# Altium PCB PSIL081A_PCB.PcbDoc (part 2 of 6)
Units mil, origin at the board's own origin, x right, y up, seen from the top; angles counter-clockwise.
Board outline 14000 x 8000 mil, 10 copper layers (Top Layer, Signal Layer 1, Signal Layer 2, Signal Layer 3, Signal Layer 4, Signal Layer 5, Signal Layer 6, Signal Layer 7, Signal Layer 8, Bottom Layer), stack 60.9 mil thick; 433 components, 510 nets, 1716 pads, 590 vias.
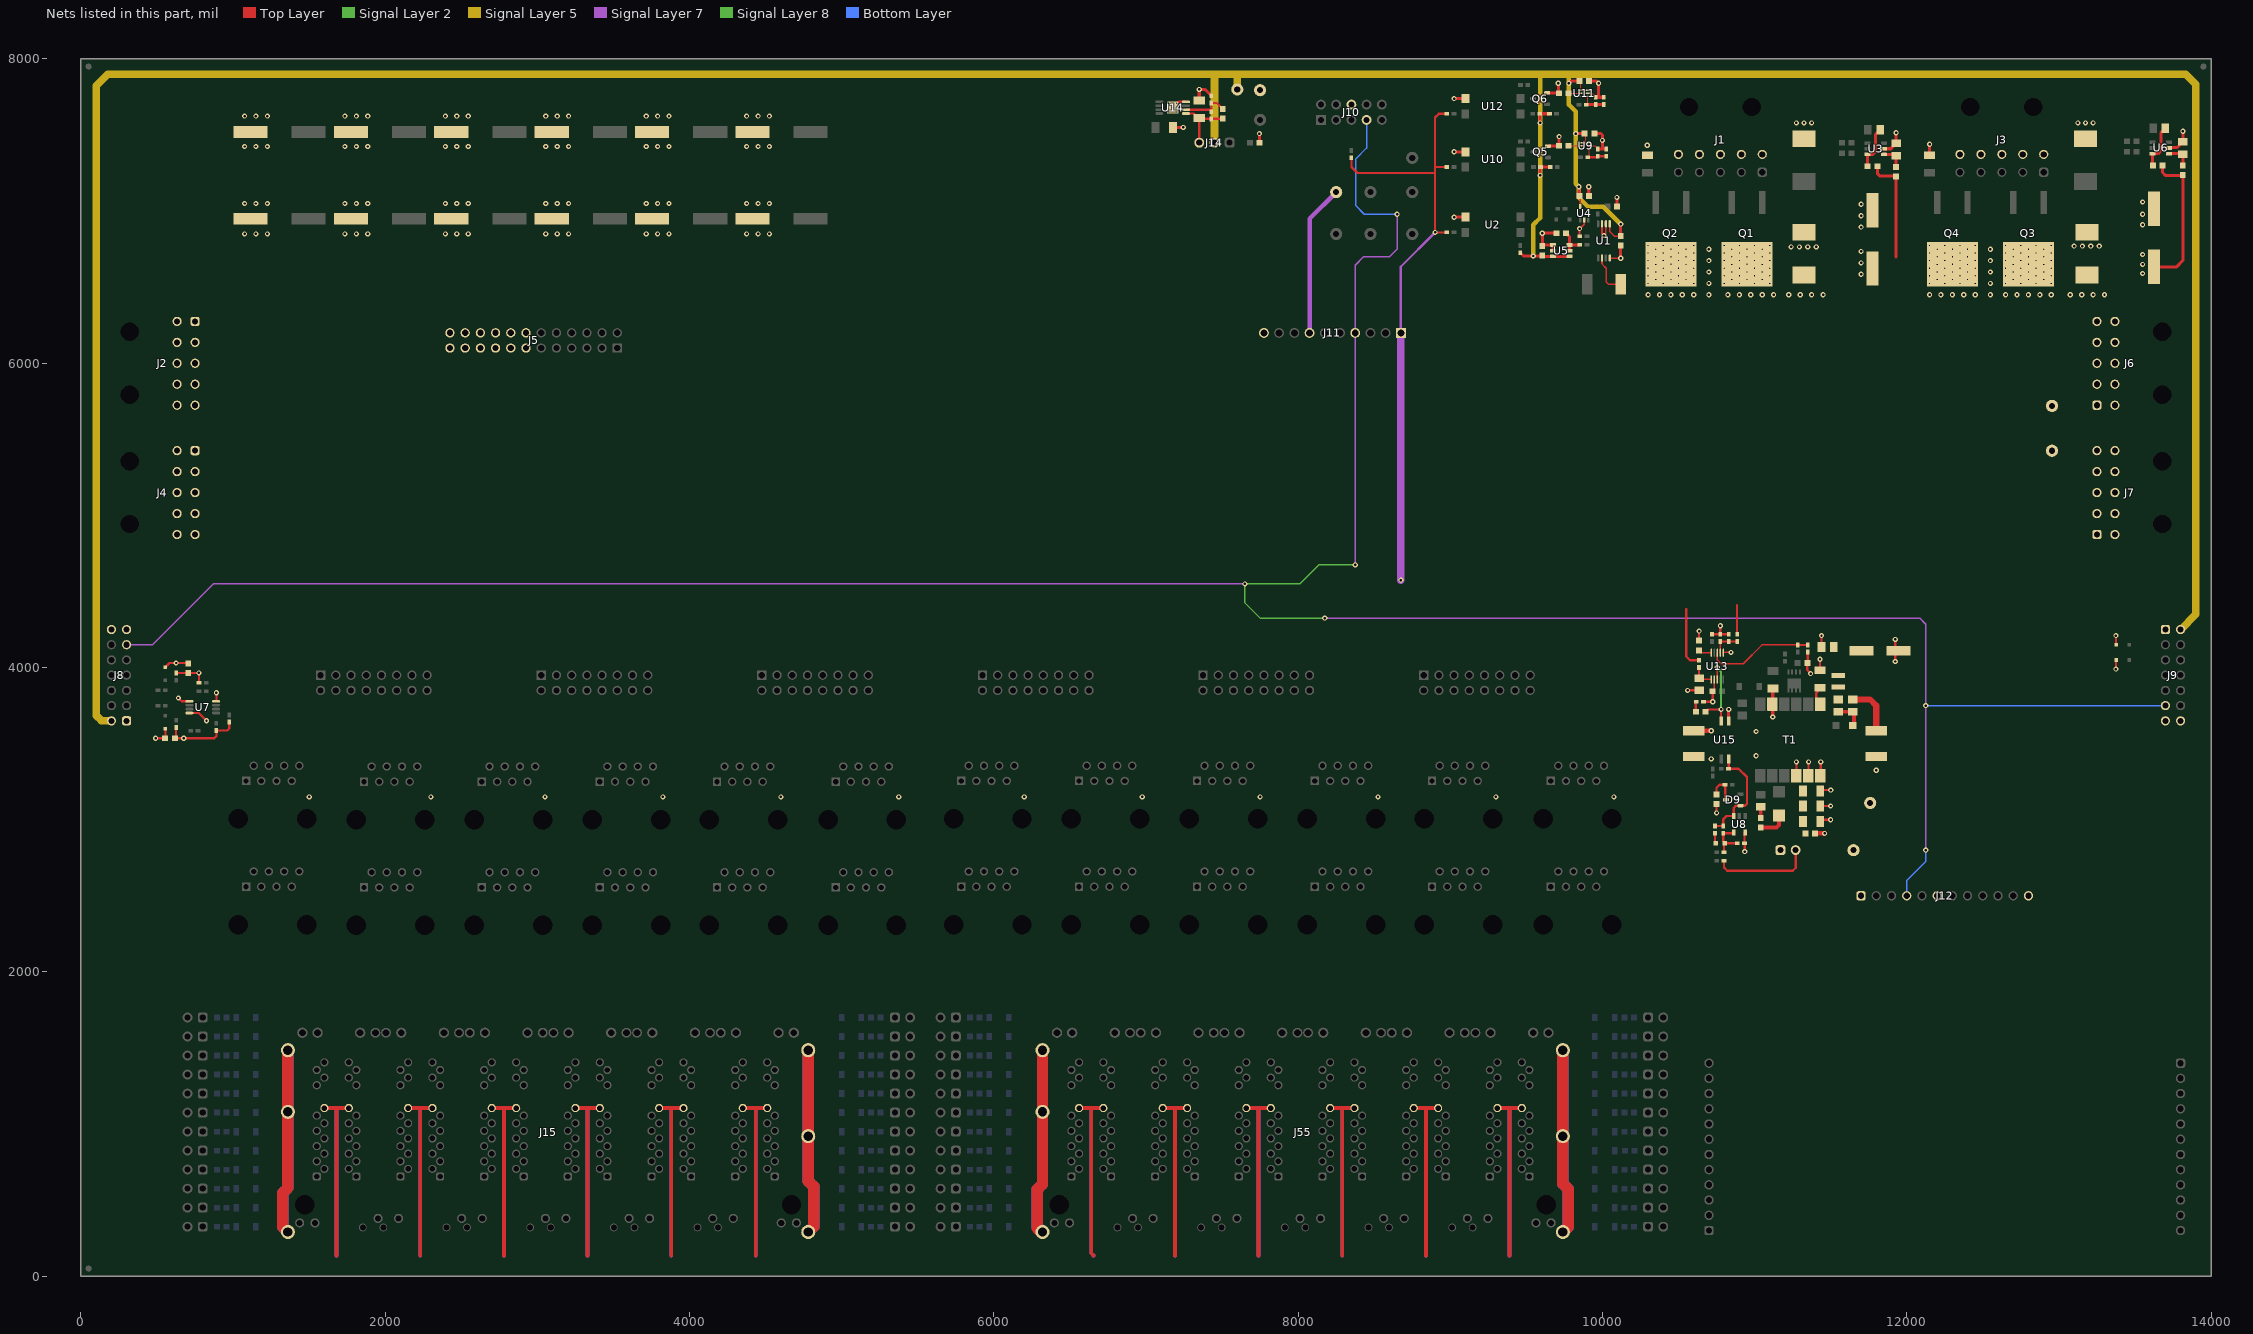
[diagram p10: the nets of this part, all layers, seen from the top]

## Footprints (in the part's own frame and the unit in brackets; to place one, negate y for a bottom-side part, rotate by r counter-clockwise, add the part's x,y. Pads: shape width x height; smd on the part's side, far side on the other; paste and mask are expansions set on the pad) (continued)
Samtec_SSW-112-21-x-S [mm] "Receptacle, 2.54mm, 12x1, TH"
  rrect50% 1.56x1.56 hole 1.04: 1(-13.97,0)
  round 1.56 hole 1.04: 2(-11.43,0) 3(-8.89,0) 4(-6.35,0) 5(-3.81,0) 6(-1.27,0) 7(1.27,0) 8(3.81,0) 9(6.35,0) 10(8.89,0) 11(11.43,0) 12(13.97,0)
  body extent -15.49,-1.21 15.49,1.21, height 8.51
Samtec_TST-107-01-G-D [mm] "Header(shrouded), 2.54mm, 7x2, TH"
  rrect50% 1.53x1.53 hole 1.02: 1(-1.27,7.62)
  round 1.53 hole 1.02: 2(1.27,7.62) 3(-1.27,5.08) 4(1.27,5.08) 5(-1.27,2.54) 6(1.27,2.54) 7(-1.27,0) 8(1.27,0) 9(-1.27,-2.54) 10(1.27,-2.54) 11(-1.27,-5.08) 12(1.27,-5.08) 13(-1.27,-7.62) 14(1.27,-7.62)
  silkscreen extent -4.9,-12.7 4.83,12.7, body extent -4.44,-12.7 4.84,12.7, height 9.27
SM_RADIAL_E [mm] "8 x 6.2mm:  Panasonic E"
  rect 4x1.6 smd: 1(-3.1,0) 2(3.1,0)
  silkscreen extent -4.25,-4.25 4.25,4.25, body extent -4.25,-4.25 4.25,4.25, height 6.5
SM_RADIAL_H13 [mm] "12.5 x 13.5mm:  Panasonic H13"
  rect 5.7x2 smd: 1(-4.85,0) 2(4.85,0)
  silkscreen extent -6.85,-6.85 6.85,6.85, body extent -6.85,-6.85 6.85,6.85, height 14
SMA [mm] "Molded Diode, 2-Leads, Body 4.3x2.6mm, IPC Medium Density, based on OnSemi component dimensions and land pattern"
  rect 2x2 smd: 1(-2,0) 2(2,0)
  silkscreen extent -3.66,-1.57 2.79,1.57, body extent -2.6,-1.3 2.6,1.3, height 2.42
SMC [mil] "Molded Diode, 2-Leads, Body 6.9x5.8mm, IPC Medium Density, based on OnSemi component dimensions and land patterns"
  rect 110x150 smd: 1(-140.49,0) 2(140.49,0)
  silkscreen extent -221,-123 189,124, body extent -156,-116 156,116, height 91
SOD-123 [mm] "On Semi recommended land pattern"
  rect 0.915x1.22 smd: 1(-1.637,0) 2(1.637,0)
  silkscreen extent -2.74,-1.17 2.03,1.17, body extent -1.93,-0.9 1.93,0.9, height 1.35
SOD-123F [mm] "NXP recommended land pattern"
  rect 1.2x1.2 smd paste-0.05: 1(-1.4,0) 2(1.4,0)
  silkscreen extent -2.64,-1.12 2.01,1.12, body extent -1.8,-0.85 1.8,0.85, height 1.2
SOD-323 [mm] "NXP recommended land pattern"
  rect 0.6x0.6 smd paste-0.05: 1(-1.1,0) 2(1.1,0)
  silkscreen extent -2.06,-0.86 1.53,0.86, body extent -1.3,-0.67 1.3,0.68, height 1.1
SOT-23 [mm] "SOT23, 3-Leads, Body 2.9x1.3mm, Pitch 0.95mm, Lead Span 2.5mm, IPC Medium Density"
  rrect50% 1x0.6 smd: 1(-1.2,0.95) 2(-1.2,-0.95) 3(1.2,0)
  silkscreen extent -1.62,-1.5 0.7,1.5, body extent -1.16,-1.45 1.21,1.45, height 1
SPC02SYAN [mil] "SULLINS"
  round 1 on Mech3: 0(0,0)
  body extent -98,-47 99,47, height 366
TI_Stacked_Overlay_Small [mil]
  silkscreen extent -418,-98 418,98
TSW-102-07-G-S [mm] "Samtec 100mil, 1x2, 230 mil above insulator"
  rrect50% 1.65x1.65 hole 1.016: 1(-1.27,0)
  round 1.65 hole 1.016: 2(1.27,0)
  body extent -2.54,-1.27 2.54,1.27, height 8.38
TSW-103-07-G-S [mm] "Samtec 100mil, 1x3, 230 mil above insulator"
  rrect50% 1.65x1.65 hole 1.016: 1(-2.54,0)
  round 1.65 hole 1.016: 2(0,0) 3(2.54,0)
  body extent -3.81,-1.27 3.81,1.27, height 8.38
WE-MAPI_2510 [mm] "SMD, 2-Leads, Body 2.7x2.2mm"
  rect 0.85x2.3 smd: 1(-0.975,0) 2(0.975,0)
  silkscreen extent -0.15,-1.1 0.15,1.1, body extent -1.25,-1 1.25,1, height 1
WEEE_Minimum [mil] "WEEElie bin"
  silkscreen extent -95,-172 99,104
Wurth_EP11_5 [mm] "SMD, 12-Leads, Body 9.2x12.9mm, Pitch 2mm"
  rrect6% 2.25x1.75 smd: 1(-5.975,5) 2(-5.975,3) 3(-5.975,1) 4(-5.975,-1) 5(-5.975,-3) 6(-5.975,-5) 7(5.975,-5) 8(5.975,-3) 9(5.975,-1) 10(5.975,1) 11(5.975,3) 12(5.975,5)
  body extent -6.5,-6.45 6.5,6.45, height 6.2

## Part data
C1 C6: library part CMP-0011225-2, "CAP, AL, 47 uF, 100 V, +/- 20%, 0.32 ohm, AEC-Q200 Grade 2, SMD", Cap_Case=H13, Manufacturer=Panasonic, Supplier Part Number 1=PCE3497CT-ND, Tolerance_%=20%, Value1="0.32 ohm", Value2=100V, ValueDisplayed=47uF
C2 C5 C23 C24 C28 C30 C54 C55: library part CMP-0006829-4, "CAP, CERM, 0.1 uF, 16 V, +/- 10%, X7R, 0603", Cap_Case=0603, Manufacturer="Wurth Elektronik", Supplier Part Number 1=710-885012206046, TempCo=X7R, Tolerance_%=10%, Value1=Unknown, Value2=16V, ValueDisplayed=0.1uF
C3 C9 C32 C46: library part CMP-0750068-1, "CAP, CERM, 1 µF, 100 V,+/- 10%, X7R, 1206", Cap_Case=1206, Manufacturer=AVX, TempCo=X7R, Tolerance_%=10%, Value2=100V, ValueDisplayed=1µF
C4 C10 C33 C37 C53 C56 C57: library part CMP-0007886-2, "CAP, CERM, 0.1 uF, 100 V, +/- 10%, X7R, 0805", Cap_Case=0805, Manufacturer=TDK, Supplier Part Number 1=445-1418-1-ND, TempCo=X7R, Tolerance_%=10%, Value1="0.020726 ohm", Value2=100V, ValueDisplayed=0.1uF
C7 C8: library part CMP-0007138-4, "CAP, CERM, 0.47 uF, 16 V, +/- 10%, X7R, AEC-Q200 Grade 1, 0603", Cap_Case=0603, Manufacturer=MuRata, Supplier Part Number 1=490-4775-1-ND, TempCo=X7R, Tolerance_%=10%, Value1=Unknown, Value2=16V, ValueDisplayed=0.47uF
C11 C12 C13 C14 C15 C16 C17 C18 C19 C20 C21 C22: library part CMP-0011226-2, "CAP, AL, 68 uF, 100 V, +/- 20%, 0.32 ohm, AEC-Q200 Grade 2, SMD", Cap_Case=H13, Manufacturer=Panasonic, Supplier Part Number 1=PCE3498CT-ND, Tolerance_%=20%, Value1="0.32 ohm", Value2=100V, ValueDisplayed=68uF
C25 C26: library part CMP-0006822-4, "CAP, CERM, 100 pF, 50 V, +/- 5%, C0G/NP0, 0603", Cap_Case=0603, Manufacturer="Wurth Elektronik", TempCo=C0G/NP0, Tolerance_%=5%, Value1=Unknown, Value2=50V, ValueDisplayed=100pF
C27 C29 C38: library part CMP-0006229-2, "CAP, CERM, 1000 pF, 25 V, +/- 10%, X7R, 0402", Cap_Case=0402, Manufacturer="Wurth Elektronik", Supplier Part Number 1=710-885012205044, TempCo=X7R, Tolerance_%=10%, Value1=Unknown, Value2=25V, ValueDisplayed=1000pF
C31: library part CMP-0064933-4, "CAP, CERM, 1000 pF, 50 V,+/- 10%, X7R, 0603", Cap_Case=0603, Manufacturer="Wurth Elektronik", Supplier Part Number 1=732-8001-1-ND, TempCo=X7R, Tolerance_%=10%, Value1=Unknown, Value2=50V, ValueDisplayed=1000pF
C34 C35 C36 C48: library part CMP-0009020-2, "CAP, CERM, 22 uF, 6.3 V, +/- 20%, X5R, 1206", Cap_Case=1206, Manufacturer="Taiyo Yuden", Supplier Part Number 1=1463395, TempCo=X5R, Tolerance_%=20%, Value1="0.012 ohm", Value2=6.3V, ValueDisplayed=22uF
C39: library part CMP-0006836-4, "CAP, CERM, 0.022 uF, 50 V, +/- 10%, X7R, 0603", Cap_Case=0603, Manufacturer="Wurth Elektronik", TempCo=X7R, Tolerance_%=10%, Value1=Unknown, Value2=50V, ValueDisplayed=0.022uF
C40 C49: library part CMP-0006831-4, "CAP, CERM, 1 uF, 16 V, +/- 10%, X7R, 0603", Cap_Case=0603, Manufacturer="Wurth Elektronik", Supplier Part Number 1=710-885012206052, TempCo=X7R, Tolerance_%=10%, Value1=Unknown, Value2=16V, ValueDisplayed=1uF
C41 C44: library part CMP-0006217-2, "CAP, CERM, 100 pF, 50 V, +/- 5%, C0G/NP0, 0402", Cap_Case=0402, Manufacturer="Wurth Elektronik", Supplier Part Number 1=732-7475-1-ND, TempCo=C0G/NP0, Tolerance_%=5%, Value1=Unknown, Value2=50V, ValueDisplayed=100pF
C42: library part CMP-0750070-1, "CAP, CERM, 10 µF, 16 V,+/- 10%, X7R, 1206", Cap_Case=1206, Manufacturer="Wurth Elektronik", TempCo=X7R, Tolerance_%=10%, Value2=16V, ValueDisplayed=10µF
C43: library part CMP-0750069-1, "CAP, CERM, 0.068 µF, 25 V,+/- 10%, X7R, 0603", Cap_Case=0603, Manufacturer="Wurth Elektronik", TempCo=X7R, Tolerance_%=10%, Value2=25V, ValueDisplayed=0.068µF
C45: library part CMP-0086483-1, "0.047µF ±10% 25V Ceramic Capacitor X7R 0603 (1608 Metric)", Manufacturer="Wurth Electronics", TempCo=15%, Tolerance_%=10%
C47: library part CMP-0750039-1, "CAP, CERM, 0.01 µF, 50 V,+/- 10%, X7R, 0603", Cap_Case=0603, Manufacturer="Wurth Elektronik", TempCo=X7R, Tolerance_%=10%, Value2=50V, ValueDisplayed=0.01µF
C50 C51: library part CMP-0009358-2, "CAP, CERM, 2200 pF, 2000 V, +/- 10%, X7R, 1812", Cap_Case=1812, Manufacturer=TDK, Supplier Part Number 1=445-2389-1-ND, TempCo=X7R, Tolerance_%=10%, Value1=Unknown, Value2=2000V, ValueDisplayed=2200pF
C52: library part CMP-0011189-2, "CAP, AL, 22 uF, 63 V, +/- 20%, 1.2 ohm, AEC-Q200 Grade 2, SMD", Cap_Case=E, Manufacturer=Panasonic, Supplier Part Number 1=PCE3820CT-ND, Tolerance_%=20%, Value1="1.2 ohm", Value2=63V, ValueDisplayed=22uF
C58: library part CMP-0007136-5, "CAP, CERM, 1 uF, 16 V, +/- 10%, X7R, AEC-Q200 Grade 1, 0603", Cap_Case=0603, Manufacturer=MuRata, Supplier Part Number 1=490-5241-6-ND, TempCo=X7R, Tolerance_%=10%, Value1=Unknown, Value2=16V, ValueDisplayed=1uF
D1 D4: library part CMP-0005716-3, "Diode, TVS, Uni, 58 V, 93.6 Vc, SMC", Manufacturer="Diodes Inc.", Value1=1500W
D2 D5: library part CMP-0028411-2, "Diode, Schottky, 100 V, 3 A, SMC", Manufacturer="Diodes Inc.", Value1=3A, Value2=0.79V
D3 D58 D59 D60 D61: library part CMP-0028458-2, "Diode, Schottky, 30 V, 0.2 A, SOD-323", Manufacturer="Diodes Inc.", Value1=0.2A, Value2=0.7V
D6: library part CMP-0028401-1, "Diode, Schottky, 30 V, 2 A, SMA", Manufacturer="Diodes Inc.", Supplier Part Number 1=B230A-FDICT-ND, Value1=2A, Value2=0.5V
D7: library part CMP-0750076-1, "Diode, Superfast Rectifier, 200 V, 0.7 A, SOD-123F", Manufacturer=Rohm, Value1=0.7A, Value2=0.85V
D8: library part CMP-0029032-1, "Diode, Switching, 100 V, 0.2 A, SOD-123", Manufacturer="ON Semiconductor", Supplier Part Number 1=MMSD4148T1GOSCT-ND, Value1=0.2A, Value2=1V
D9: library part CMP-0028456-1, "Diode, Schottky, 30 V, 0.2 A, SOT-23", Manufacturer="Diodes Inc.", Supplier Part Number 1=BAT54S-FDICT-ND, Value1=0.2A, Value2=0.65V
D10 D11 D12 D13 D14 D15 D16 D17 D18 D19 D20 D21 D22 D23 D24 D25 D26 D27 D28 D29 D30 D31 D32 D33 D34 D35 D36 D37 D38 D39 D40 D41 D42 D43 D44 D45 D46 D47 D48 D49 D50 D51 D52 D53 D54 D55 D56 D57: library part CMP-0005757-2, "Diode, Zener, 22 V, 500 mW, SOD-123", Manufacturer="Diodes Inc.", Power_W=500mW, Supplier Part Number 1=MMSZ5251B-FDICT-ND, Value1=0.5W
FID1 FID2 FID3 FID4 FID5 FID6: library part CMP-0077181-1, "Fiducial mark.  There is nothing to buy or mount.", Manufacturer=N/A
H1 H2 H3 H4 H5 H6 H7 H8 H9 H10 H11 H12: library part CMP-0079645-1, Manufacturer=3M, Supplier Part Number 1=SJ61A6-ND
J1 J2 J3 J4 J6 J7: library part CMP-0085662-1, "Header(shrouded), 3.5mm, 5x2, Gold, R/A, TH", Color=Black, Manufacturer=Molex, Voltage_V=400V
J5: library part CMP-0750080-1, "Receptacle, 2.54mm, 12x2, Gold, TH", Color=Black, Current_A=4.7A, Manufacturer=Samtec, Voltage_V=655V
J8 J9: library part CMP-0078831-2, "Header(shrouded), 2.54mm, 7x2, Gold, TH", Color=Black, Current_A=3.4A, Manufacturer=Samtec, Supplier Part Number 1=SAM10833-ND, Voltage_V=1kV
J10: library part CMP-0055448-2, "Header (shrouded), 100mil, 5x2, High-Temperature, Gold, TH", Manufacturer=3M, Supplier Part Number 1=MHC10K-ND
J11: library part CMP-0750079-1, "Receptacle, 2.54mm, 10x1, Gold, TH", Color=Black, Current_A=4.7A, Manufacturer=Samtec, Voltage_V=655V
J12 J95 J96: library part CMP-0750078-1, "Receptacle, 2.54mm, 12x1, Gold, TH", Color=Black, Current_A=4.7A, Manufacturer=Samtec, Voltage_V=655V
J13 J17 J19 J21 J22 J23 J24 J26 J28 J30 J31 J32 J33 J38 J40 J42 J43 J44 J45 J47 J49 J51 J52 J53 J54 J57 J59 J61 J62 J63 J64 J66 J68 J70 J71 J72 J73 J78 J80 J82 J83 J84 J85 J87 J89 J91 J92 J93 J94: library part CMP-0075405-2, "Header, 100mil, 2x1, Gold, TH", Color=Black, Current_A=6.3A, Manufacturer=Samtec, Supplier Part Number 1=SAM1029-02-ND, Voltage_V=550V
J14: library part CMP-0075407-2, "Header, 100mil, 3x1, Gold, TH", Color=Black, Current_A=6.3A, Manufacturer=Samtec, Supplier Part Number 1=SAM1029-03-ND, Voltage_V=550V
J15 J55: library part CMP-0081711-4, "12 Port RJ45, R/A, TH", Manufacturer="Pulse Engineering", Supplier Part Number 1=553-3937-ND
J16 J18 J20 J25 J27 J29 J37 J39 J41 J46 J48 J50 J56 J58 J60 J65 J67 J69 J77 J79 J81 J86 J88 J90: library part CMP-0055855-1, "RJ45, Vertical, TH", Manufacturer="Stewart Connector", Supplier Part Number 1=380-1050-ND
J34 J35 J36 J74 J75 J76: library part CMP-0750077-1, "Receptacle, 2.54mm, 8x2, Gold, TH", Color=Black, Current_A=4.7A, Manufacturer=Samtec, Voltage_V=655V
L1: library part CMP-0750073-1, "Inductor, Shielded, Metal Composite, 3.3 µH, 1.25 A, 0.264 ohm, SMD", Manufacturer="Wurth Elektronik", Value1="0.264 ohm", Value2=1.25A, ValueDisplayed=3.3µH
Logo1: library part CMP-0074838-1, "Texas Instrument Corporate Signature"
Logo2: library part CMP-0074844-1
Logo3: library part CMP-0074847-1, "FCC_disclaimer"
Logo4: library part CMP-0074769-1
Q1 Q2 Q3 Q4: library part CMP-0000966-3, "MOSFET, N-CH, 100 V, 200 A, KTT0002A (TO-263-2)", Alternate Manufacturer=None, Manufacturer="Texas Instruments", Supplier Part Number 1=296-41136-1-ND, Value2="118 nC"
Q5 Q6: library part CMP-0000419-2, "Transistor, NPN, 40 V, 0.2 A, SOT-23", Manufacturer="ON Semiconductor", Supplier Part Number 1=MMBT3904LT1GOSCT-ND, Value1="0.2 A", Value2=300
Q7: library part CMP-0001051-2, "MOSFET, N-CH, 150 V, 13 A, PG-TSDSON-8", Alternate Manufacturer=None, Manufacturer="Infineon Technologies", Supplier Part Number 1="BSZ900N15NS3 GCT-ND", Value2="5 nC"
R1 R6: library part CMP-0025700-4, "RES, 100, 5%, 0.1 W, AEC-Q200 Grade 0, 0603", Manufacturer=Vishay-Dale, Power_W=100mW, Supplier Part Number 1=541-100GCT-ND, TempCo="200 ppm/C", Tolerance_%=5%, Value2=0.1W, Value_Code=100R, ValueDisplayed=100
R2 R20 R23 R35 R45: library part CMP-0026071-3, "RES, 1.00 k, 1%, 0.063 W, AEC-Q200 Grade 0, 0402", Manufacturer=Vishay-Dale, Power_W=63mW, Supplier Part Number 1=541-1.00KLCT-ND, TempCo="100 ppm/C", Tolerance_%=1%, Value2=0.063W, Value_Code=1k00, ValueDisplayed=1.00k
R3 R21 R24: library part CMP-0026329-2, "RES, 3.01 k, 1%, 0.063 W, AEC-Q200 Grade 0, 0402", Manufacturer=Vishay-Dale, Power_W=63mW, Supplier Part Number 1=541-3.01KLCT-ND, TempCo="100 ppm/C", Tolerance_%=1%, Value2=0.063W, Value_Code=3k01, ValueDisplayed=3.01k
R4: library part CMP-0015822-2, "RES, 0.0005, 1%, 3 W, 2512", Manufacturer="Stackpole Electronics Inc", Power_W=3W, Supplier Part Number 1=HCS2512FTL500CT-ND, TempCo="115 ppm/C", Tolerance_%=1%, Value_Code=L5000, ValueDisplayed=0.0005
R5: library part CMP-0026367-2, "RES, 40.2 k, 1%, 0.063 W, AEC-Q200 Grade 0, 0402", Manufacturer=Vishay-Dale, Power_W=63mW, Supplier Part Number 1=541-40.2KLCT-ND, TempCo="100 ppm/C", Tolerance_%=1%, Value2=0.063W, Value_Code=40k2, ValueDisplayed=40.2k
R7 R9 R10 R11 R12 R13 R42 R43: library part CMP-0025958-3, "RES, 10.0 k, 1%, 0.063 W, AEC-Q200 Grade 0, 0402", Manufacturer=Vishay-Dale, Power_W=63mW, Supplier Part Number 1=541-10.0KLCT-ND, TempCo="100 ppm/C", Tolerance_%=1%, Value2=0.063W, Value_Code=10k0, ValueDisplayed=10.0k
R8: library part CMP-0026516-2, "RES, 6.65 k, 1%, 0.063 W, AEC-Q200 Grade 0, 0402", Manufacturer=Vishay-Dale, Power_W=63mW, Supplier Part Number 1=541-6.65KLCT-ND, TempCo="100 ppm/C", Tolerance_%=1%, Value2=0.063W, Value_Code=6k65, ValueDisplayed=6.65k
R14 R15 R18 R39 R44 R97 R104 R105: library part CMP-0026992-3, "RES, 0, 5%, 0.1 W, AEC-Q200 Grade 0, 0402", Manufacturer=Panasonic, Power_W=100mW, Supplier Part Number 1=P0.0JCT-ND, TempCo="600 ppm/C", Tolerance_%=5%, Value2=0.1W, Value_Code=0000, ValueDisplayed=0
R16 R17: library part CMP-0026404-2, "RES, 49.9, 1%, 0.063 W, AEC-Q200 Grade 0, 0402", Manufacturer=Vishay-Dale, Power_W=63mW, Supplier Part Number 1=541-49.9LCT-ND, TempCo="100 ppm/C", Tolerance_%=1%, Value2=0.063W, Value_Code=49R9, ValueDisplayed=49.9
R19 R22: library part CMP-0026414-2, "RES, 4.99 k, 1%, 0.063 W, AEC-Q200 Grade 0, 0402", Manufacturer=Vishay-Dale, Power_W=63mW, Supplier Part Number 1=541-4.99KLCT-ND, TempCo="100 ppm/C", Tolerance_%=1%, Value2=0.063W, Value_Code=4k99, ValueDisplayed=4.99k
R25 R26: library part CMP-0026158-2, "RES, 200 k, 1%, 0.063 W, AEC-Q200 Grade 0, 0402", Manufacturer=Vishay-Dale, Power_W=63mW, Supplier Part Number 1=541-200KLCT-ND, TempCo="100 ppm/C", Tolerance_%=1%, Value2=0.063W, Value_Code=200k
R27 R28: library part CMP-0026465-2, "RES, 5.36 k, 1%, 0.063 W, AEC-Q200 Grade 0, 0402", Manufacturer=Vishay-Dale, Power_W=63mW, Supplier Part Number 1=541-5.36KLCT-ND, TempCo="100 ppm/C", Tolerance_%=1%, Value2=0.063W, Value_Code=5k36, ValueDisplayed=5.36k
R29: library part CMP-0020567-3, "RES, 51, 5%, 0.125 W, AEC-Q200 Grade 0, 0805", Manufacturer=Vishay-Dale, Power_W=125mW, Supplier Part Number 1=541-51ACT-ND, TempCo="200 ppm/C", Tolerance_%=5%, Value2=0.125W, Value_Code=51R0, ValueDisplayed=51
R30: library part CMP-0020536-3, "RES, 39 k, 5%, 0.125 W, AEC-Q200 Grade 0, 0805", Manufacturer=Vishay-Dale, Power_W=125mW, Supplier Part Number 1=541-39KACT-ND, TempCo="200 ppm/C", Tolerance_%=5%, Value2=0.125W, Value_Code=39k0, ValueDisplayed=39k
R31 R34: library part CMP-0026827-3, "RES, 10, 5%, 0.063 W, AEC-Q200 Grade 0, 0402", Manufacturer=Vishay-Dale, Power_W=63mW, Supplier Part Number 1=541-10JCT-ND, TempCo="200 ppm/C", Tolerance_%=5%, Value2=0.063W, Value_Code=10R0, ValueDisplayed=10
R32 R46: library part CMP-0025950-3, "RES, 100 k, 1%, 0.063 W, AEC-Q200 Grade 0, 0402", Manufacturer=Vishay-Dale, Power_W=63mW, Supplier Part Number 1=541-100KLCT-ND, TempCo="100 ppm/C", Tolerance_%=1%, Value2=0.063W, Value_Code=100k
R33: library part CMP-0020497-3, "RES, 20, 5%, 0.125 W, AEC-Q200 Grade 0, 0805", Manufacturer=Vishay-Dale, Power_W=125mW, Supplier Part Number 1=541-20ACT-ND, TempCo="200 ppm/C", Tolerance_%=5%, Value2=0.125W, Value_Code=20R0, ValueDisplayed=20
R36: library part CMP-0026336-2, "RES, 3.57 k, 1%, 0.063 W, AEC-Q200 Grade 0, 0402", Manufacturer=Vishay-Dale, Power_W=63mW, Supplier Part Number 1=541-3.57KLCT-ND, TempCo="100 ppm/C", Tolerance_%=1%, Value2=0.063W, Value_Code=3k57, ValueDisplayed=3.57k
R37: library part CMP-0026201-2, "RES, 25.5 k, 1%, 0.063 W, AEC-Q200 Grade 0, 0402", Manufacturer=Vishay-Dale, Power_W=63mW, Supplier Part Number 1=541-25.5KLCT-ND, TempCo="100 ppm/C", Tolerance_%=1%, Value2=0.063W, Value_Code=25k5, ValueDisplayed=25.5k
R38: library part CMP-0022193-4, "RES, 1.74, 1%, 0.1 W, AEC-Q200 Grade 0, 0603", Manufacturer=Vishay-Dale, Power_W=100mW, Supplier Part Number 1=541-1.74HHCT-ND, TempCo="100 ppm/C", Tolerance_%=1%, Value2=0.1W, Value_Code=1R74, ValueDisplayed=1.74
R40: library part CMP-0026088-3, "RES, 1.50 k, 1%, 0.063 W, AEC-Q200 Grade 0, 0402", Manufacturer=Vishay-Dale, Power_W=63mW, Supplier Part Number 1=541-1.50KLCT-ND, TempCo="100 ppm/C", Tolerance_%=1%, Value2=0.063W, Value_Code=1k50, ValueDisplayed=1.50k
R41: library part CMP-0026185-2, "RES, 237, 1%, 0.063 W, AEC-Q200 Grade 0, 0402", Manufacturer=Vishay-Dale, Power_W=63mW, Supplier Part Number 1=541-237LCT-ND, TempCo="100 ppm/C", Tolerance_%=1%, Value2=0.063W, Value_Code=237R, ValueDisplayed=237
R47: library part CMP-0026469-2, "RES, 5.90 k, 1%, 0.063 W, AEC-Q200 Grade 0, 0402", Manufacturer=Vishay-Dale, Power_W=63mW, Supplier Part Number 1=541-5.90KLCT-ND, TempCo="100 ppm/C", Tolerance_%=1%, Value2=0.063W, Value_Code=5k90, ValueDisplayed=5.90k
R48: library part CMP-0026449-2, "RES, 54.9 k, 1%, 0.063 W, AEC-Q200 Grade 0, 0402", Manufacturer=Vishay-Dale, Power_W=63mW, Supplier Part Number 1=541-54.9KLCT-ND, TempCo="100 ppm/C", Tolerance_%=1%, Value2=0.063W, Value_Code=54k9, ValueDisplayed=54.9k
R49 R50 R51 R52 R53 R54 R55 R56 R57 R58 R59 R60 R61 R62 R63 R64 R65 R66 R67 R68 R69 R70 R71 R72 R73 R74 R75 R76 R77 R78 R79 R80 R81 R82 R83 R84 R85 R86 R87 R88 R89 R90 R91 R92 R93 R94 R95 R96: library part CMP-0022352-4, "RES, 35.7 k, 1%, 0.1 W, AEC-Q200 Grade 0, 0603", Manufacturer=Vishay-Dale, Power_W=100mW, Supplier Part Number 1=541-35.7KHCT-ND, TempCo="100 ppm/C", Tolerance_%=1%, Value2=0.1W, Value_Code=35k7, ValueDisplayed=35.7k
R98 R99 R100 R101 R102 R103: library part CMP-0025703-4, "RES, 10, 5%, 0.1 W, AEC-Q200 Grade 0, 0603", Manufacturer=Vishay-Dale, Power_W=100mW, Supplier Part Number 1=541-10GCT-ND, TempCo="200 ppm/C", Tolerance_%=5%, Value2=0.1W, Value_Code=10R0, ValueDisplayed=10
SH-J1 SH-J2 SH-J3 SH-J4 SH-J5 SH-J6 SH-J7 SH-J8 SH-J9 SH-J10 SH-J11 SH-J12 SH-J13 SH-J14 SH-J15 SH-J16 SH-J17 SH-J18 SH-J19 SH-J20 SH-J21 SH-J22 SH-J23 SH-J24 SH-J25 SH-J26 SH-J27 SH-J28 SH-J29 SH-J30 SH-J31 SH-J32 SH-J33 SH-J34 SH-J35 SH-J36 SH-J37 SH-J38 SH-J39 SH-J40 SH-J41 SH-J42 SH-J43 SH-J44 SH-J45 SH-J46 SH-J47 SH-J48 SH-J49 SH-J50: library part CMP-0003642-1, "Shunt, 100mil, Flash Gold, Black", Manufacturer="Sullins Connector Solutions", Supplier Part Number 1=S9001-ND
T1: library part CMP-0084630-1, "Transformer, 400 uH, SMT", Manufacturer="Wurth Elektronik", ValueDisplayed=400µH
TP1 TP8 TP10 TP11: library part CMP-0055137-1, "Test Point, Miniature, Red, TH", Color=Red, Manufacturer=Keystone, PartNumber=5000, Supplier Part Number 1=36-5000-ND
TP2 TP9 TP12 TP13: library part CMP-0055138-1, "Test Point, Miniature, Black, TH", Color=Black, Manufacturer=Keystone, PartNumber=5001, Supplier Part Number 1=36-5001-ND
TP3: library part CMP-0055141-1, "Test Point, Miniature, Yellow, TH", Color=Yellow, Manufacturer=Keystone, PartNumber=5004, Supplier Part Number 1=36-5004-ND
TP4 TP5 TP14: library part CMP-0055139-1, "Test Point, Miniature, White, TH", Color=White, Manufacturer=Keystone, PartNumber=5002, Supplier Part Number 1=36-5002-ND
TP6 TP7: library part CMP-0055140-1, "Test Point, Miniature, Orange, TH", Color=Orange, Manufacturer=Keystone, PartNumber=5003, Supplier Part Number 1=36-5003-ND
U1: library part CMP-0075735-1, "High/Low Side, Bi-Directional Zero-Drift Current Sense Amp w/ Enhanced PWM Rejection, PW0008A (TSSOP-8)", Alternate Manufacturer="Texas Instruments", Alternate PartNumber=INA240A2PW
U2 U10 U12: library part CMP-0006165-3, "Optocoupler, 5 kV, 300-600% CTR, SMT", Manufacturer="Fairchild Semiconductor", Supplier Part Number 1=FOD817DS-ND, Voltage_Isolation_Vrms=5kV
U3 U6: library part CMP-0066129-2, "High Side OR-ing FET Controller, DDC0006A (SOT-23-T-6)", Alternate Manufacturer="Texas Instruments"
U4: library part CMP-0085889-2, "Small-Size Micropower Low-Voltage Comparator, DCK0005A (SOT-SC70-5)", Alternate Manufacturer="Texas Instruments", Alternate PartNumber=TLV7021DCKT, Operating Temperature Range="-40 to 125 C", Rating=Catalog
U5: library part CMP-0083672-1, "2.5V Low-Drift Low-Power Small-Footprint Series Voltage Reference, DBV0006A (SOT-23-6)", Alternate Manufacturer="Texas Instruments", Operating Temperature Range="-40 to 125 C", Rating=Catalog
U7: library part CMP-0065788-2, "Level-Translating I2C Bus Repeater, DGK0008A (VSSOP-8)", Alternate Manufacturer="Texas Instruments"
U8: library part CMP-0032952-1, "Low Voltage Adjustable Precision Shunt Regulator, 39 ppm / degC, 15 mA, -40 to 85 degC, 5-pin SOT-23 (DBV), Green (RoHS & no Sb/Br)", Manufacturer="Texas Instruments", Rating=Catalog, Temp Coeff(Max)(ppm/ degree C)=129, Temp Coeff(Typ)(ppm/ degree C)=39
U9 U11: library part CMP-0074273-2, "Low Quiescent Current, 1% Accurate Supervisor with Programmable-Delay, DSE0006A (WSON-6)", Alternate Manufacturer="Texas Instruments", Alternate PartNumber=TPS389001DSET
U13: library part CMP-0066105-1, "13-100V Wide Vin, Current Mode PWM Boost Controller, DGS0010A (VSSOP-10)", Alternate Manufacturer="Texas Instruments"
U14: library part CMP-0035942-1, "Single Output LDO, 50 mA, Adjustable 1.175 to 90 V Output, 7 to 100 V Input, 8-pin MSOP (DGN), -40 to 125 degC, Green (RoHS & no Sb/Br)", Manufacturer="Texas Instruments"
U15: library part CMP-0006164-3, "Optocoupler, 3.75 kV, 80-160% CTR, SMT", Manufacturer="Fairchild Semiconductor", Supplier Part Number 1=HMHA2801A-ND, Voltage_Isolation_Vrms=3.75kV
ZZ2: library part CMP-0077236-1
ZZ3: library part CMP-0077237-1
ZZ4: library part CMP-0077238-1

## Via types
v1: diameter 34, hole 16, Top Layer to Bottom Layer, 429 vias
v2: diameter 26, hole 8, Top Layer to Bottom Layer, 156 vias
v3: diameter 19.68, hole 7.87, Top Layer to Bottom Layer, 5 vias

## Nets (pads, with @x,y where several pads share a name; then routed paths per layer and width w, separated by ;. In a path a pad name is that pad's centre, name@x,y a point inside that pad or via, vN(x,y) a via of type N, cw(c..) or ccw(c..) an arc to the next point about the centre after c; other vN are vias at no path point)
3.3V: C2.2 C5.2 C7.2 C28.2 C30.2 J8.2 J9.2 J14.2 R2.1 R19.1 R20.1 R22.1 R23.1 TP11.1 U1.5 U4.5 U5.3 U5.4 U9.3 U9.4 U11.3 U11.4 | length 25971.4
  Top Layer w8: C30.2@9848.5,7855 9856.38,7847.13 U11.4@9856.38,7794.69 U11.3@9903.62,7794.69 ; U9.4@9866.38,7449.69 9890,7449.69 ; C28.2@9883.5,7510 9890,7503.5 9890,7449.69 ; U9.3@9913.62,7449.69 9890,7449.69
  Top Layer w10: U1.5@10048.39,6917.2 10048.39,6866.61 10080,6835 10118.5,6835 C2.2@10120,6836.5
  Top Layer w12: C5.2@9848.5,7100 9854.41,7094.09 U4.5@9854.41,7029.29
  Top Layer w20: R2.1@9460,6726.38 9481.38,6705 v1(9545,6705) 9601.5,6705 C7.2@9605,6708.5 9610.59,6702.91 U5.3@9675.87,6702.91 U5.4@9784.13,6702.91 ; v1(9590,7235) 9590,7286.38 R20.1@9593.62,7290 R19.1@9656.38,7290 ; v1(9590,7580) 9590,7638.62 R23.1@9588.62,7640 R22.1@9651.38,7640 ; v1(9780,7840) 9795,7855 C30.2@9848.5,7855 ; v1(9825,7510) C28.2@9883.5,7510 ; v1(9845,7160) 9845,7103.5 C5.2@9848.5,7100 ; C2.2@10120,6836.5 v1(10120,6915)
  Signal Layer 5 w30: v1(9545,6705) 9545,6910 9590,6955 v1(9590,7235) v1(9590,7580) 9590,7900 ; 9780,7900 v1(9780,7840) 9780,7700 9825,7655 v1(9825,7510) 9825,7180 v1(9845,7160) 9845.55,7159.45 9845.55,7090 9905.55,7030 10005,7030 v1(10120,6915)
  Signal Layer 5 w50: J8.2@200,3650 135,3650 100,3685 100,7825 175,7900 7455,7900 ; J14.2@7450,7450 7450,7895 7455,7900 ; TP11.1@7600,7800 7600,7900 ; J9.2@13800,4250 13900,4350 13900,7835 13835,7900 9780,7900 9590,7900 7600,7900 ; 7455,7900 7600,7900
3.3V_ISO: C23.1 C24.1 J8.1 J9.1 J11.1 J12.1 J13.1 R3.1 R9.1 R10.1 R11.1 R12.1 R13.1 R21.1 R24.1 R97.1 TP10.1 U7.1 U7.8 | length 4878.8
  Top Layer w15: R10.1@625,3606.38 625,3543.5 C23.1@616.5,3535 v1(675,3535) 875,3535 890,3550 R11.1@890,3586.38 961.38,3586.38 975,3600 R12.1@975,3641.38 ; R9.1@625,3963.62 704.88,3963.62 706.26,3965 v1(775,3965) 775,3901.38 R13.1@776.38,3900 ; v1(640,3800) 661.61,3778.39 U7.1@712.4,3778.39 ; U7.8@887.6,3778.39 890,3780.79 v1(890,3835) ; R97.1@8350,7351.38 8350,7290 8390,7250 8900,7250 ; R3.1@8976.38,6860 v1(8900,6860) 8900,7250 ; R21.1@8976.38,7290 8900,7290 ; R24.1@8976.38,7640 8925,7640 8900,7615 8900,7290 ; 8900,7250 8900,7290
  Signal Layer 7 w15: J11.1@8675,6200 8675,6635 v1(8900,6860)
  Signal Layer 7 w50: v1(8675,4575) J11.1@8675,6200
55VDC: C1.1 C6.1 C52.1 C53.2 D1.1 D4.1 J2.1 J2.2 J2.3 J2.4 J2.5 J4.1 J4.2 J4.3 J4.4 J4.5 J6.1 J6.2 J6.3 J6.4 J6.5 J7.1 J7.2 J7.3 J7.4 J7.5 L1.1 Q1.2 Q2.2 Q3.2 Q4.2 R1.2 R4.2 R6.2 R31.1 R32.1 R100.1 R103.1 TP1.1 U1.2 | length 2526.6
  Top Layer w10: U1.2@9997.2,6692.8 9997.2,6652.8 10025,6625 10025,6535 10040,6520 R4.2@10112.36,6520
  Top Layer w15: 10550,4385 10550,4075 10576.38,4048.62 R31.1@10635,4048.62 ; R32.1@10885,4218.62 10885,4410
  Top Layer w20: R100.1@11806.5,7295 11806.5,7248.5 11825,7230 11928.5,7230 R1.2@11930,7228.5 11930,6700 ; C6.1@13625,6634.06 13774.06,6634.06 13815,6675 R6.2@13815,7238.51 13811.49,7235 13700,7235 13681.5,7253.5 R103.1@13681.5,7300
  other v1: 10300,6450 10375,6450 10450,6450 10525,6450 10600,6450 10700,6450 10825,6450 10900,6450 10975,6450 11050,6450 11125,6450 11225,6450 11300,6450 11375,6450 11450,6450 12150,6450 12225,6450 12300,6450 12375,6450 12450,6450 12550,6450 12650,6450 12725,6450 12800,6450 12875,6450 12950,6450 13075,6450 13150,6450 13225,6450 13300,6450 10700,6525 12550,6525 11700,6585 13550,6590 10700,6600 12550,6600 13550,6650 11700,6660 10700,6675 12550,6675 13550,6715 11700,6735 10700,6750 12550,6750
  other v2: 10300,6525 10400,6525 10500,6525 10600,6525 10800,6525 10900,6525 11000,6525 11100,6525 12150,6525 12250,6525 12350,6525 12450,6525 12650,6525 12750,6525 12850,6525 12950,6525 10350,6550 10450,6550 10550,6550 10850,6550 10950,6550 11050,6550 12200,6550 12300,6550 12400,6550 12700,6550 12800,6550 12900,6550 10300,6575 10400,6575 10500,6575 10600,6575 10800,6575 10900,6575 11000,6575 11100,6575 12150,6575 12250,6575 12350,6575 12450,6575 12650,6575 12750,6575 12850,6575 12950,6575 10350,6600 10450,6600 10550,6600 10850,6600 10950,6600 11050,6600 12200,6600 12300,6600 12400,6600 12700,6600 12800,6600 12900,6600 10300,6625 10400,6625 10500,6625 10600,6625 10800,6625 10900,6625 11000,6625 11100,6625 12150,6625 12250,6625 12350,6625 12450,6625 12650,6625 12750,6625 12850,6625 12950,6625 10350,6650 10550,6650 10850,6650 11050,6650 12200,6650 12400,6650 12700,6650 12900,6650 10450,6651.14 10950,6651.14 12300,6651.14 12800,6651.14 10300,6675 10400,6675 10500,6675 10600,6675 10800,6675 10900,6675 11000,6675 11100,6675 12150,6675 12250,6675 12350,6675 12450,6675 12650,6675 12750,6675 12850,6675 12950,6675 10350,6700 10450,6700 10550,6700 10850,6700 10950,6700 11050,6700 12200,6700 12300,6700 12400,6700 12700,6700 12800,6700 12900,6700 10300,6725 10400,6725 10500,6725 10600,6725 10800,6725 10900,6725 11000,6725 11100,6725 12150,6725 12250,6725 12350,6725 12450,6725 12650,6725 12750,6725 12850,6725 12950,6725 10350,6750 10450,6750 10550,6750 10850,6750 10950,6750 11050,6750 12200,6750 12300,6750 12400,6750 12700,6750 12800,6750 12900,6750 10300,6775 10400,6775 10500,6775 10600,6775 10800,6775 10900,6775 11000,6775 11100,6775 12150,6775 12250,6775 12350,6775 12450,6775 12650,6775 12750,6775 12850,6775 12950,6775
BSP: J15.A10 J15.B10 J15.C10 J15.D10 J15.E10 J15.F10 J15.G10 J15.H10 J15.I10 J15.J10 J15.K10 J15.L10 J15.S1 J15.S2 J15.S3 J15.S4 J15.S5 J15.S6 J55.A10 J55.B10 J55.C10 J55.D10 J55.E10 J55.F10 J55.G10 J55.H10 J55.I10 J55.J10 J55.K10 J55.L10 J55.S1 J55.S2 J55.S3 J55.S4 J55.S5 J55.S6 | length 36930.8
  Top Layer w25: J15.A10@1599.92,1104.96 1680,1104.96 ; 1680,135 1680,1104.96 ; J15.B10@1760.16,1104.96 1680,1104.96 ; J15.C10@2149.92,1104.96 2230,1104.96 ; 2230,135 2230,1104.96 ; J15.D10@2310.16,1104.96 2230,1104.96 ; J15.E10@2699.92,1104.96 2780.04,1104.96 ; 2780,135 2780.04,135.04 2780.04,1104.96 ; J15.F10@2860.16,1104.96 2780.04,1104.96 ; J15.G10@3249.92,1104.96 3330,1104.96 ; 3330,135 3330,1104.96 ; J15.H10@3410.16,1104.96 3330,1104.96 ; J15.I10@3799.92,1104.96 3880,1104.96 ; 3880,135 3880,1104.96 ; J15.J10@3960.16,1104.96 3880,1104.96 ; J15.K10@4349.92,1104.96 4435,1104.96 ; 4435,135 4435,1104.96 ; J15.L10@4510.16,1104.96 4435,1104.96 ; J55.A10@6559.92,1104.96 6640.04,1104.96 ; 6655,135 6640.04,149.96 6640.04,1104.96 ; J55.B10@6720.16,1104.96 6640.04,1104.96 ; J55.C10@7109.92,1104.96 7190,1104.96 ; 7190,135 7190,1104.96 ; J55.D10@7270.16,1104.96 7190,1104.96 ; J55.E10@7659.92,1104.96 7740,1104.96 ; 7740,135 7740,1104.96 ; J55.F10@7820.16,1104.96 7740,1104.96 ; J55.G10@8209.92,1104.96 8290.04,1104.96 ; 8290,135 8290.04,135.04 8290.04,1104.96 ; J55.H10@8370.16,1104.96 8290.04,1104.96 ; J55.I10@8759.92,1104.96 8840,1104.96 ; 8840,135 8840,1104.96 ; J55.J10@8920.16,1104.96 8840,1104.96 ; J55.K10@9309.92,1104.96 9390.04,1104.96 ; 9390,135 9390.04,135.04 9390.04,1104.96 ; J55.L10@9470.16,1104.96 9390.04,1104.96
  Top Layer w75: J15.S1@1359.96,290 1325,324.96 1325,545 1359.96,579.96 J15.S2@1359.96,1079.76 J15.S3@1359.96,1484.88 ; J15.S4@4780.04,290 4815,324.96 4815,590 4780.04,624.96 J15.S5@4780.04,919.92 J15.S6@4780.04,1484.88 ; J55.S1@6315,285.04 6285,315.04 6285,570 6319.96,604.96 J55.S2@6319.96,1079.76 J55.S3@6319.96,1484.88 ; J55.S4@9740.04,290 9775,324.96 9775,572.42 9740.04,607.38 J55.S5@9740.04,919.92 J55.S6@9740.04,1484.88
  Bottom Layer w25: J15.A10@1599.92,1104.96 1680,1104.96 ; 1680,135 1680,1104.96 ; J15.B10@1760.16,1104.96 1680,1104.96 ; J15.C10@2149.92,1104.96 2230,1104.96 ; 2230,135 2230,1104.96 ; J15.D10@2310.16,1104.96 2230,1104.96 ; J15.E10@2699.92,1104.96 2780.04,1104.96 ; 2780,135 2780.04,135.04 2780.04,1104.96 ; J15.F10@2860.16,1104.96 2780.04,1104.96 ; J15.G10@3249.92,1104.96 3330,1104.96 ; 3330,135 3330,1104.96 ; J15.H10@3410.16,1104.96 3330,1104.96 ; J15.I10@3799.92,1104.96 3880,1104.96 ; 3880,135 3880,1104.96 ; J15.J10@3960.16,1104.96 3880,1104.96 ; J15.K10@4349.92,1104.96 4435,1104.96 ; 4435,135 4435,1104.96 ; J15.L10@4510.16,1104.96 4435,1104.96 ; J55.A10@6559.92,1104.96 6640.04,1104.96 ; 6655,135 6640.04,149.96 6640.04,1104.96 ; J55.B10@6720.16,1104.96 6640.04,1104.96 ; J55.C10@7109.92,1104.96 7190,1104.96 ; 7190,135 7190,1104.96 ; J55.D10@7270.16,1104.96 7190,1104.96 ; J55.E10@7659.92,1104.96 7740,1104.96 ; 7740,135 7740,1104.96 ; J55.F10@7820.16,1104.96 7740,1104.96 ; J55.G10@8209.92,1104.96 8290.04,1104.96 ; 8290.04,135.04 8290.04,1104.96 ; J55.H10@8370.16,1104.96 8290.04,1104.96 ; J55.I10@8759.92,1104.96 8840,1104.96 ; 8840,135 8840,1104.96 ; J55.J10@8920.16,1104.96 8840,1104.96 ; J55.K10@9309.92,1104.96 9390.04,1104.96 ; 9390,135 9390.04,135.04 9390.04,1104.96 ; J55.L10@9470.16,1104.96 9390.04,1104.96
  Bottom Layer w75: J15.S1@1359.96,290 1325,324.96 1325,545 1359.96,579.96 J15.S2@1359.96,1079.76 J15.S3@1359.96,1484.88 ; J15.S4@4780.04,290 4815,324.96 4815,590 4780.04,624.96 J15.S5@4780.04,919.92 J15.S6@4780.04,1484.88 ; J55.S1@6319.96,290 6285,324.96 6285,570 6319.96,604.96 J55.S2@6319.96,1079.76 J55.S3@6319.96,1484.88 ; J55.S4@9740.04,290 9775,324.96 9775,572.42 9740.04,607.38 J55.S5@9740.04,919.92 J55.S6@9740.04,1484.88
GND: C1.2 C2.1 C3.1 C4.2 C5.1 C6.2 C7.1 C8.1 C9.1 C10.2 C11.2 C12.2 C13.2 C14.2 C15.2 C16.2 C17.2 C18.2 C19.2 C20.2 C21.2 C22.2 C25.1 C26.1 C27.1 C28.1 C29.1 C30.1 C32.1 C37.2 C38.1 C39.1 C40.1 C41.1 C42.1 C46.2 C48.2 C51.2 C52.2 C53.1 C55.1 C58.1 D1.2 D2.2 D4.2 D5.2 J1.6 J1.7 J1.8 J1.9 J1.10 J2.6 J2.7 J2.8 J2.9 J2.10 J3.6 J3.7 J3.8 J3.9 J3.10 J4.6 J4.7 J4.8 J4.9 J4.10 J5.13 J5.14 J5.15 J5.16 J5.17 J5.18 J5.19 J5.20 J5.21 J5.22 J5.23 J5.24 J6.6 J6.7 J6.8 J6.9 J6.10 J7.6 J7.7 J7.8 J7.9 J7.10 J8.14 J9.14 J11.10 Q5.2 Q6.2 R8.1 R27.2 R28.2 R36.2 R37.2 R38.2 R40.2 R48.2 T1.5 TP2.1 TP9.1 U1.4 U1.6 U1.7 U3.2 U4.2 U5.1 U5.2 U6.2 U9.2 U11.2 U13.2 U13.6 U14.4 U14.9 U15.3 | length 3854.3
  Top Layer w8: U11.2@9903.62,7775 9928.62,7775 R28.2@9955,7748.62 ; U9.2@9913.62,7430 9948.62,7430 R27.2@9970,7408.62
  Top Layer w10: U1.7@9997.2,6917.2 9997.2,6852.8 v1(10010,6840) 10022.8,6852.8 U1.6@10022.8,6917.2 ; U1.4@10048.39,6692.8 10051.18,6690 v1(10120,6690) ; C40.1@10723.5,3845 10735.31,3856.81 U13.2@10735.31,3922.4 ; U13.6@10794.37,4097.6 10796.77,4100 v1(10845,4100)
  Top Layer w12: R8.1@9851.38,6835 9850,6836.38 v1(9850,6885) 9880,6915 U4.2@9880,6940.71
  Top Layer w15: v3(7175,7680) 7213.39,7718.39 U14.4@7262.6,7718.39 ; v1(10560,3850) C37.2@10635,3850 ; C39.1@10635,4176.5 v1(10635,4240) ; R40.2@10663.62,3775 v1(10725,3775) 10725,3843.5 C40.1@10723.5,3845 ; R37.2@10720,4218.62 C38.1@10775,4218.62 ; v1(10775,4275) C38.1@10775,4218.62 ; R36.2@10830,4218.62 C38.1@10775,4218.62 ; C41.1@11350,4101.38 11350,4033.5 R38.2@11346.5,4030 11346.5,3983.5 v1(11368.5,3960) ; C32.1@11430,3991.93 v1(11430,4055) ; C53.1@11440,4135 v1(11440,4210) ; v1(11925,4040) 11925,4087.95 C52.2@11947.05,4110 11925,4132.05 v1(11925,4185)
  Top Layer w20: C46.2@7186.93,7550 v1(7245,7550) ; C48.2@7350,7736.93 v1(7350,7800) 7388.62,7800 R48.2@7430,7758.62 ; v1(7745,7510) 7745,7451.5 C55.1@7746.5,7450 ; Q6.2@9637.24,7777.4 C26.1@9711.1,7777.4 ; Q5.2@9642.24,7427.4 9710.91,7427.4 C25.1@9713.5,7430 9715,7431.5 v1(9715,7490) ; U5.2@9675.87,6740.31 U5.1@9675.87,6777.72 9611.22,6777.72 C7.1@9605,6771.5 v1(9605,6855) C8.1@9698.5,6855 ; v1(9710,7840) 9710,7778.5 C26.1@9711.1,7777.4 ; C26.1@9713.5,7775 C26.1@9711.1,7777.4 ; v1(9910,7160) 9910,7101.5 C5.1@9911.5,7100 ; C30.1@9911.5,7855 9960,7855 v1(9975,7840) 9975,7748.62 ; C28.1@9946.5,7510 9990,7510 10000,7500 v1(10000,7465) 10000,7408.62 ; R28.2@9955,7748.62 9975,7748.62 ; R27.2@9970,7408.62 10000,7408.62 ; C29.1@10010,7748.62 9975,7748.62 ; C27.1@10025,7408.62 10000,7408.62 ; v1(10095,7090) 10095,7031.5 C58.1@10096.5,7030 ; v1(10120,6690) C2.1@10120,6773.5 ; U15.3@10830,3650 v1(10830,3725) ; U3.2@11849.13,7410 11895,7410 C4.2@11930,7445 v1(11930,7515) ; C9.1@12150,7376.93 v1(12150,7440) ; U6.2@13724.14,7415 13724.14,7417.88 13777.88,7417.88 C10.2@13815,7455 v1(13815,7525)
  Top Layer w25: v1(11120,3675) 11120,3757.13 T1.5@11116.89,3760.24 11120,3763.35 C42.1@11120,3853.07
  Top Layer w30: C51.2@10600,3585 v1(10715,3585)
  other v1: 1500,3150 2300,3150 3050,3150 3825,3150 4600,3150 5375,3150 6200,3150 6975,3150 7750,3150 8525,3150 9300,3150 10075,3150 11010,3580 11240,6765 11295,6765 11350,6765 11405,6765 13100,6770 13155,6770 13210,6770 13265,6770 1075,6850 1150,6850 1225,6850 1735,6850 1810,6850 1885,6850 2395,6850 2470,6850 2545,6850 3055,6850 3130,6850 3205,6850 3715,6850 3790,6850 3865,6850 4375,6850 4450,6850 4525,6850 11700,6895 13550,6910 11700,6970 13550,6980 11700,7045 1075,7050 1150,7050 1225,7050 1735,7050 1810,7050 1885,7050 2395,7050 2470,7050 2545,7050 3055,7050 3130,7050 3205,7050 3715,7050 3790,7050 3865,7050 4375,7050 4450,7050 4525,7050 13550,7060 1075,7425 1150,7425 1225,7425 1735,7425 1810,7425 1885,7425 2395,7425 2470,7425 2545,7425 3055,7425 3130,7425 3205,7425 3715,7425 3790,7425 3865,7425 4375,7425 4450,7425 4525,7425 10295,7433 11275,7580 11325,7580 11375,7580 13125,7580 13175,7580 13225,7580 1075,7625 1150,7625 1225,7625 1735,7625 1810,7625 1885,7625 2395,7625 2470,7625 2545,7625 3055,7625 3130,7625 3205,7625 3715,7625 3790,7625 3865,7625 4375,7625 4450,7625 4525,7625
  other v3: 7147.83,7650.87 7202.17,7650.87 7147.83,7709.13 7202.17,7709.13
GND_ISO: C23.2 C24.2 C34.1 C35.1 C36.1 C49.1 C50.1 C51.1 C54.1 D58.2 D59.2 D60.2 D61.2 J8.13 J9.13 J10.6 J11.7 J12.6 J12.12 R47.2 T1.10 T1.11 T1.12 TP12.1 TP13.1 U2.3 U7.4 U8.5 U10.3 U12.3 | length 2472.8
  Top Layer w15: v1(490,3535) C23.2@553.5,3535 555,3536.5 D59.2@555,3596.69 ; D58.2@555,4003.31 581.69,4030 701.5,4030 C24.2@705,4026.5 ; U7.4@712.4,3701.61 773.39,3701.61 v1(825,3650) ; v1(10750,3045) C49.1@10750,3103.5 ; v1(10935,2790) 10935,2843.62 R47.2@10933.62,2845 10933.62,2912.09 U8.5@10937.4,2915.87 ; T1.10@11274.37,3289.76 11275,3290.39 v1(11275,3380) ; T1.11@11353.11,3289.76 11355,3291.65 v1(11355,3380) ; C34.1@11431.72,3194.98 v1(11500.92,3194.98) ; T1.12@11431.85,3289.76 11435,3292.91 v1(11435,3380) ; C36.1@11441.93,3000 v1(11500,3000) ; C35.1@11441.93,3090 v1(11500,3090) ; v1(13375,3990) 13375,4048.31 D60.2@13376.69,4050 ; v1(13375,4210) 13375,4151.69 D61.2@13376.69,4150
  Top Layer w20: v1(9025,6960) U2.3@9099.39,6960 ; v1(9025,7390) U10.3@9099.39,7390 ; v1(9025,7740) U12.3@9099.39,7740
  Top Layer w30: C54.1@11396.5,2910 v1(11460,2910)
  Signal Layer 7 w30: J11.7@8075,6200 8075,6950 TP13.1@8250,7125
  other v1: 11800,3325 10715,3400 11010,3420 625,4030
INT: J8.11 J9.11 J10.7 J11.4 J12.4 | length 19767.5
  Signal Layer 7 w10: J8.11@300,4150 470,4150 870,4550 v1(7650,4550) ; v1(8175,4325) 12085,4325 12125,4285 v1(12125,3750) v1(12125,2800) ; v1(8375,4675) J11.4@8375,6200 8375,6645 8430,6700 8600,6700 8650,6750 v1(8650,6980)
  Signal Layer 8 w10: v1(8175,4325) 7750,4325 7650,4425 v1(7650,4550) 8010,4550 8135,4675 v1(8375,4675)
  Bottom Layer w10: J10.7@8450,7600 8450,7415 8380,7345 8380,7035 8435,6980 v1(8650,6980) ; J12.4@12000,2500 12000,2600 12125,2725 v1(12125,2800) ; v1(12125,3750) J9.11@13700,3750
NetC4_1: C4.1 R1.1 U3.1 | length 157.5
  Top Layer w20: U3.1@11849.13,7372.6 11922.4,7372.6 C4.1@11930,7365 R1.1@11930,7291.5
NetC8_2: C8.2 R7.1 U5.5 U5.6 | length 192.3
  Top Layer w20: C8.2@9761.5,6855 9784.13,6832.36 U5.6@9784.13,6777.72 ; U5.5@9784.13,6740.31 U5.6@9784.13,6777.72 ; R7.1@9851.38,6780 9849.09,6777.72 U5.6@9784.13,6777.72
NetC10_1: C10.1 R6.1 U6.1 | length 165.4
  Top Layer w20: U6.1@13724.14,7377.6 13812.4,7377.6 C10.1@13815,7375 R6.1@13815,7301.5
NetC25_2: C25.2 U9.5 | length 89.9
  Top Layer w8: C25.2@9776.5,7430 U9.5@9866.38,7430
NetC26_2: C26.2 U11.5 | length 79.9
  Top Layer w7: C26.2@9776.5,7775 U11.5@9856.38,7775
NetC27_2: C27.2 R25.2 R27.1 U9.1 | length 183.8
  Top Layer w8: R25.2@9903.62,7355 9914.41,7365.79 U9.1@9914.41,7410.31
  Top Layer w15: R25.2@9903.62,7355 9963.62,7355 R27.1@9970,7361.38 C27.2@10025,7361.38
NetC29_2: C29.2 R26.2 R28.1 U11.1 | length 156.3
  Top Layer w7: U11.1@9904.41,7755.31 9904.41,7706.97 9910,7701.38
  Top Layer w20: 9910,7701.38 R28.1@9955,7701.38 C29.2@10010,7701.38
NetC31_1: C31.1 C34.2 C35.2 C36.2 C54.2 D6.1 J13.2 R39.2 | length 835.2
  Top Layer w15: R39.2@10798.62,2730 10798.62,2686.38 10820,2665 11250,2665 11270,2685 J13.2@11270,2800
  Top Layer w25: C31.1@11040,2948.5 11143.5,2948.5 11160,2965 D6.1@11160,3026.26
NetC31_2: C31.2 R29.2 | length 73.5
  Top Layer w25: C31.2@11040,3011.5 R29.2@11040,3085
NetC32_2: C32.2 C33.2 C50.2 L1.2 R30.1 T1.1 | length 455.9
  Top Layer w15: C32.2@11430,3858.07 11405,3833.07 11405,3800 11431.85,3773.15 T1.1@11431.85,3760.24
  Top Layer w40: C33.2@11645,3790 11760,3790 11800,3750 C50.2@11800,3585
NetC33_1: C33.1 D7.1 R30.2 | length 188.9
  Top Layer w25: R30.2@11550,3710 C33.1@11645,3710 11654.47,3700.53 D7.1@11654.47,3620
NetC37_1: C37.1 R31.2 U13.1 | length 155.2
  Top Layer w10: C37.1@10635,3930 10642.6,3922.4 U13.1@10715.63,3922.4
  Top Layer w15: C37.1@10635,3930 R31.2@10635,4001.38
NetC38_2: C38.2 R32.2 R36.1 U13.7 | length 183.9
  Top Layer w10: U13.7@10774.68,4097.6 10774.68,4171.06 C38.2@10775,4171.38
  Top Layer w15: C38.2@10775,4171.38 R36.1@10830,4171.38 R32.2@10885,4171.38
NetC39_2: C39.2 U13.10 | length 87.2
  Top Layer w10: C39.2@10635,4113.5 10650.91,4097.6 U13.10@10715.63,4097.6
NetC41_2: C41.2 R35.1 U13.8 | length 704.2
  Top Layer w10: U13.8@10755,4097.6 10755,4050 10780,4025 10925,4025 11048.62,4148.62 R35.1@11285,4148.62
  Top Layer w15: R35.1@11285,4148.62 C41.2@11350,4148.62
NetC43_1: C43.1 R40.1 | length 66.2
  Top Layer w15: C43.1@10613.5,3710 10613.5,3772.13 R40.1@10616.38,3775
NetC43_2: C43.2 U13.3 U15.4 | length 547.7
  Top Layer w10: U13.3@10755,3922.4 v1(10755,4000)
  Top Layer w15: C43.2@10676.5,3710 10691.5,3725 v1(10780,3725) U15.4@10780,3650
  Signal Layer 2 w15: v1(10755,4000) 10780,3975 v1(10780,3725)
NetC44_1: C44.1 C45.1 R43.2 R47.1 U8.4 | length 283.7
  Top Layer w15: R43.2@10798.62,2785 10798.62,2837.13 C45.1@10806.5,2845 ; U8.4@10862.6,2915.87 10858.11,2911.38 C44.1@10795,2911.38 10795,2856.5 C45.1@10806.5,2845 ; R47.1@10886.38,2845 C45.1@10806.5,2845
NetC44_2: C44.2 D9.1 R44.2 R45.1 U8.3 U15.2 | length 716.5
  Top Layer w15: R44.2@10740,2958.62 C44.2@10795,2958.62 10795,3005 10815,3025 10861.73,3025 U8.3@10862.6,3024.13 10862.6,3077.6 10877.6,3092.6 D9.1@10907.24,3092.6 10937.6,3092.6 10950,3105 10950,3280 10895,3335 R45.1@10828.62,3335 10830,3336.38 U15.2@10830,3400 U15.2@10828.62,3398.62
NetC45_2: C45.2 R44.1 | length 67.8
  Top Layer w15: R44.1@10740,2911.38 10740,2848.5 C45.2@10743.5,2845
NetC47_1: C47.1 C48.1 J14.3 R46.1 U14.1 | length 413.7
  Top Layer w15: U14.1@7262.6,7641.61 7311.46,7641.61 C48.1@7350,7603.07 ; J14.3@7350,7450 C48.1@7350,7603.07 ; C47.1@7505,7608.5 7502.87,7606.38 R46.1@7430,7606.38 7353.31,7606.38 C48.1@7350,7603.07
NetC47_2: C47.2 R46.2 R48.1 U14.2 | length 301.5
  Top Layer w15: U14.2@7262.6,7667.2 7427.2,7667.2 7430,7670 R48.1@7430,7711.38 7465.12,7711.38 C47.2@7505,7671.5
NetC49_2: C49.2 D9.3 R42.2 | length 210.8
  Top Layer w15: C49.2@10750,3166.5 10750,3210 10770,3230 R42.2@10806.38,3230 10806.38,3136.38 D9.3@10812.76,3130
NetC56_2: C56.2 R100.2 U3.6 | length 297.3
  Top Layer w20: R100.2@11743.5,7295 11740.86,7297.64 U3.6@11740.86,7372.6 11777.28,7372.6 11795,7390.31 11795,7505 C56.2@11825,7535
NetC57_2: C57.2 R103.2 U6.6 | length 302.3
  Top Layer w20: R103.2@13618.5,7300 13615.87,7302.64 U6.6@13615.87,7377.6 13652.29,7377.6 13670,7395.32 13670,7515 C57.2@13700,7545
